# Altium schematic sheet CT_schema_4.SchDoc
size 292 x 258 mm
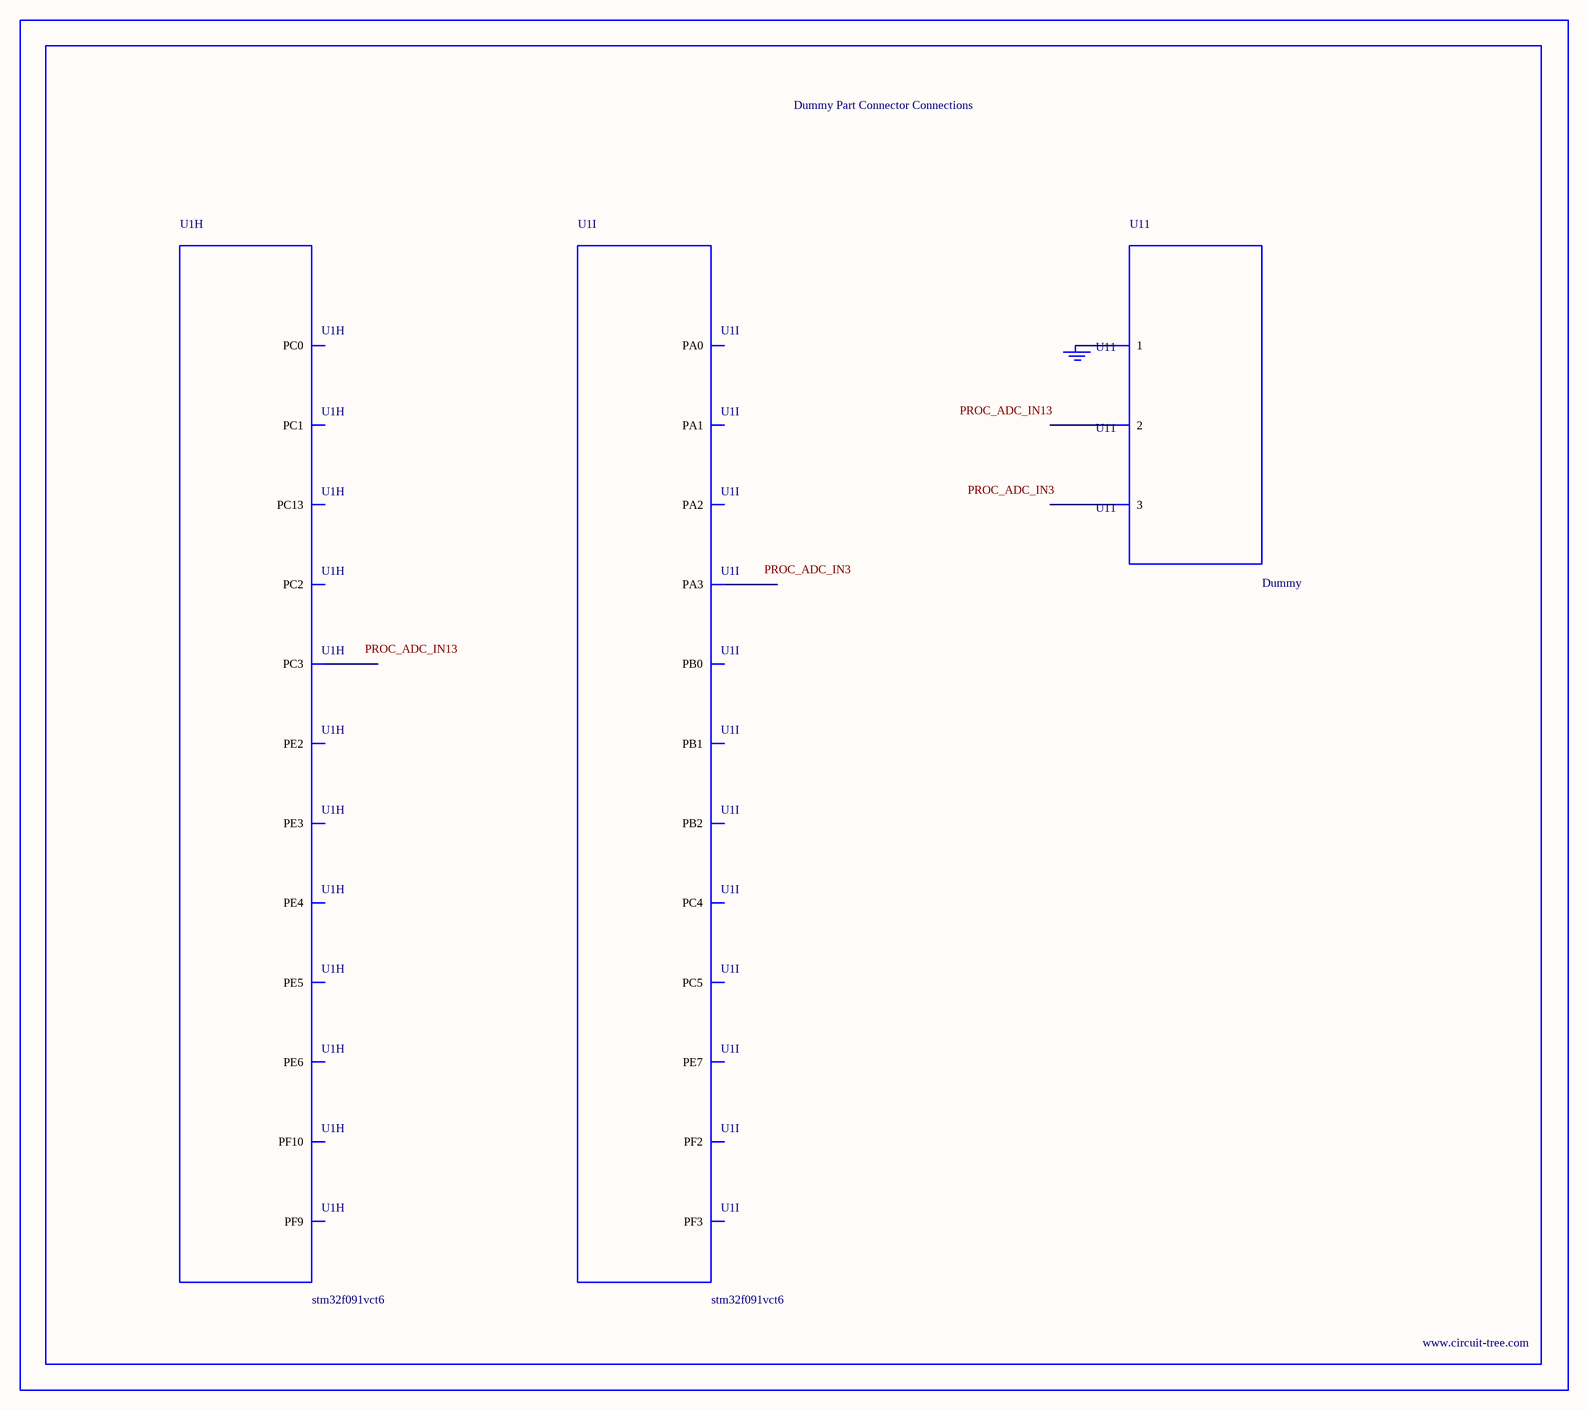
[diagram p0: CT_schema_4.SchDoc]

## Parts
BORDER3  (no value)
GND_INSTANCE_3_0  (no value)
U1  stm32f091vct6  [LQFP100]  (parts H,I of 9)
U11  Dummy  [DUMMY_PACKAGE_119]

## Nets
NetGND_INSTANCE_3_0_0: GND_INSTANCE_3_0.0(GND) U11.1

Not connected (* = marked no-connect by the designer): U1 1(PE2) 2(PE3) 3(PE4) 4(PE5) 5(PE6) 7(PC13) 10(PF9) 11(PF10) 15(PC0) 16(PC1) 17(PC2) 18(PC3) 19(PF2) 22(PF3) 23(PA0) 24(PA1) 25(PA2) 26(PA3) 33(PC4) 34(PC5) 35(PB0) 36(PB1) 37(PB2) 38(PE7); U11 2 3

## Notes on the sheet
- Labels drawn without touching a wire or pin: PROC_ADC_IN3, PROC_ADC_IN13

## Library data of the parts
BORDER3 = BORDER_PAGE3
GND_INSTANCE_3_0 = GND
